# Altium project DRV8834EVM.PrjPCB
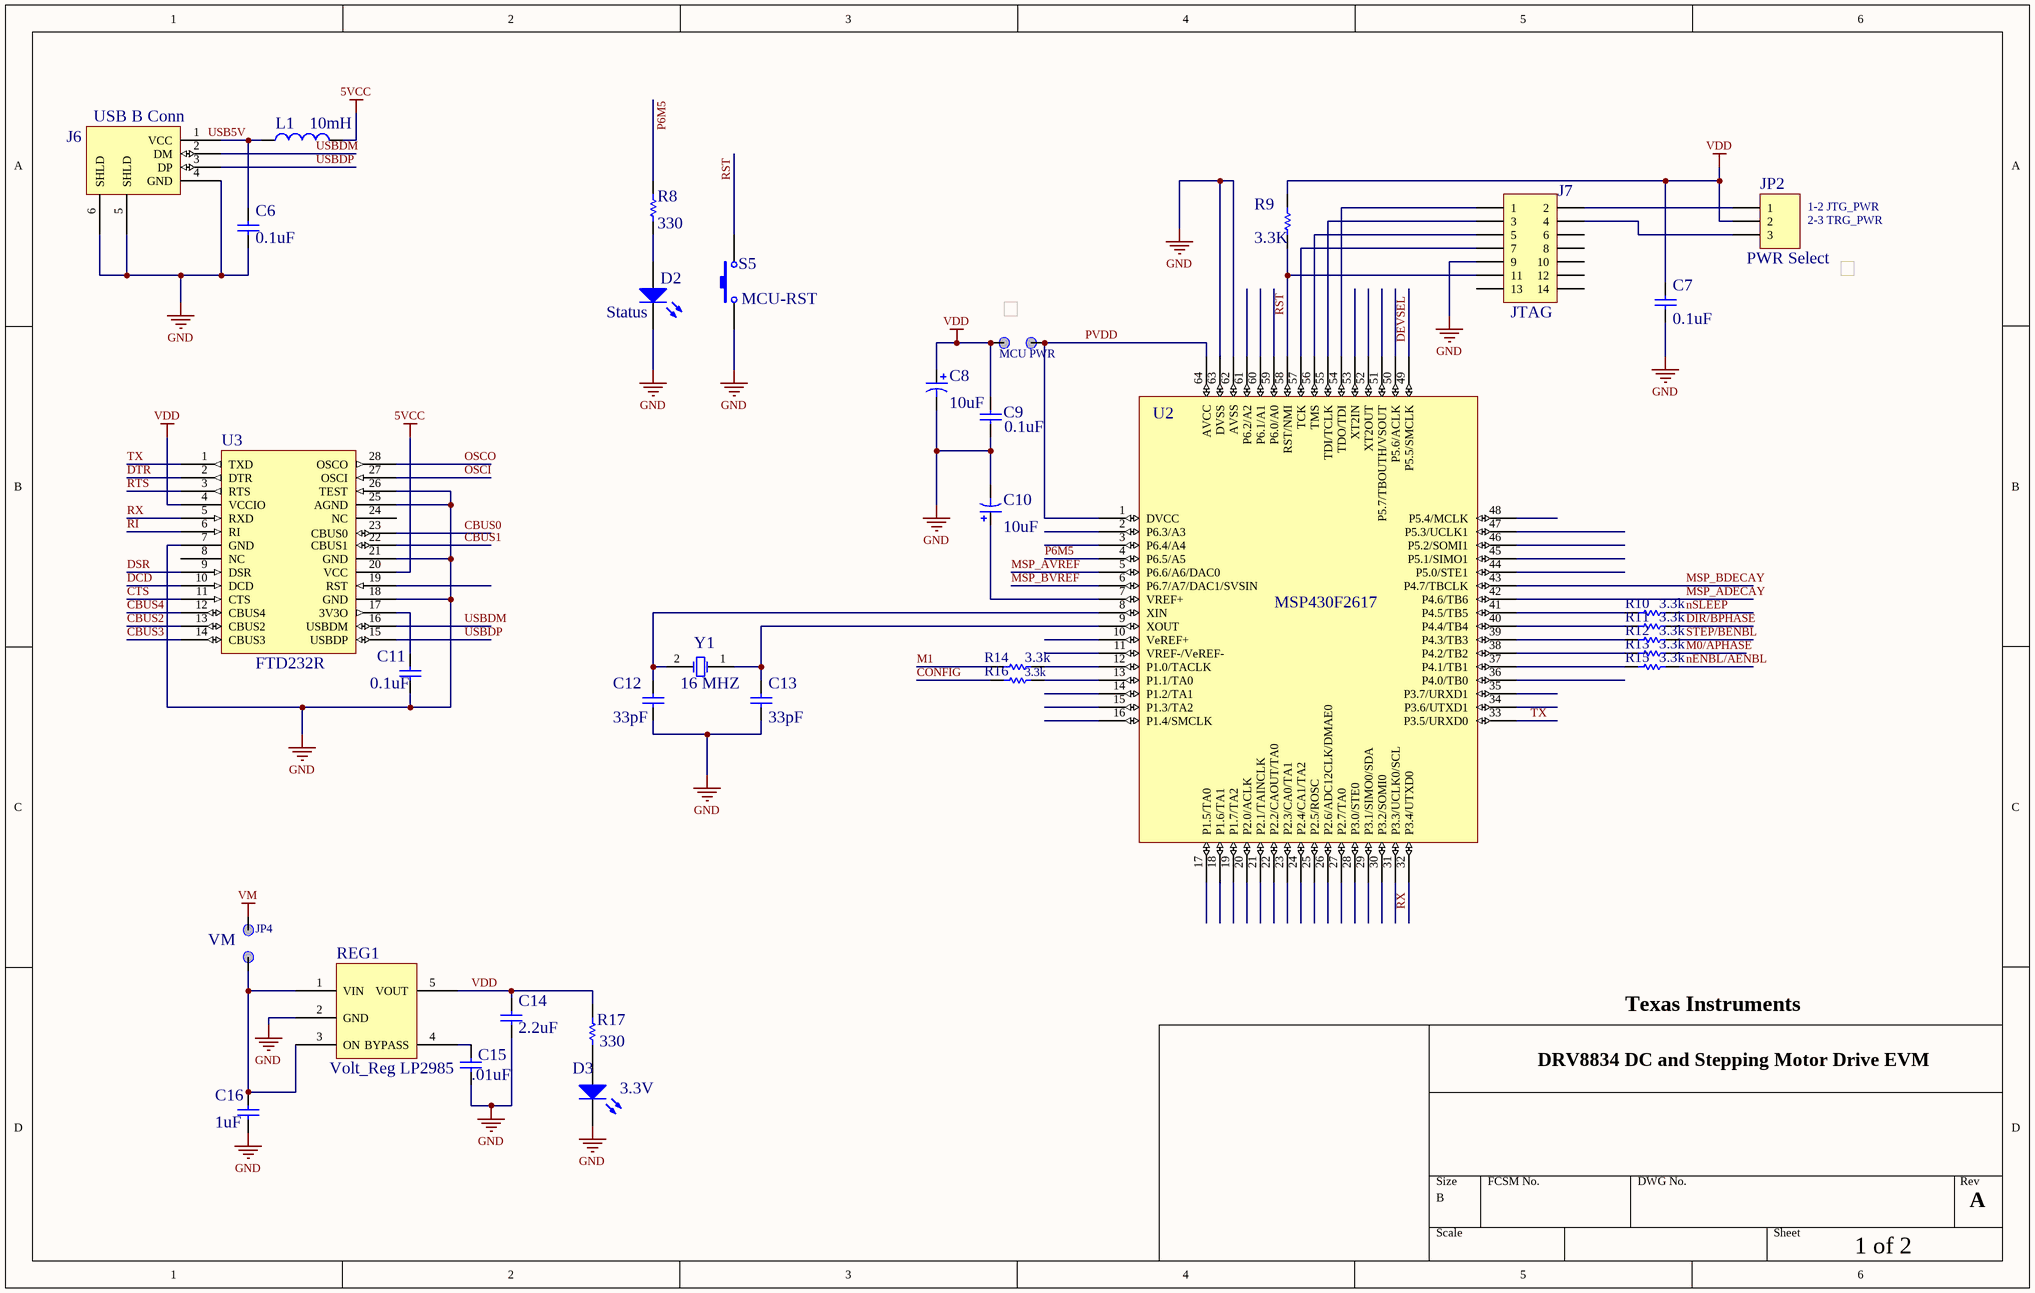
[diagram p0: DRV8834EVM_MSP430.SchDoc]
EVM_Title: DRV8834 Customer EVM- Dual H Bridge Driver
2 sheets, 87 parts. Net scope: global (net labels, ports and power ports of the same name join across sheets).
Board file: DRV8834EVM.PcbDoc
Sheets:
  DRV8834EVM_MSP430.SchDoc
  DRV8834EVM.SchDoc

## Sheet DRV8834EVM_MSP430.SchDoc
size B; PageSetup: Record=PageOptions|CenterHorizontal=True|CenterVertical=True|PrintScale=0.70|XCorrection=1.00|YCorrection=1.00|PrintKind=0|BorderSize=5000000|LeftOffset=0|BottomOffset=0|Orientation=2|PaperLength=1000|PaperWidth=1000|Scale=100|PaperSource=15|PrintQuality=600|MediaType=1|DitherType=10|PaperKind=Letter|PrintScaleMode=1

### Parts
C6  value 0.1uF  [0805]
C7  value 0.1uF  [0805]
C8  value 10uF  [RB .1/.250]  (hidden comment: Cap Pol1)
C9  value 0.1uF  [0805]
C10  value 10uF  [RB .1/.250]  (hidden comment: Cap Pol1)
C11  value 0.1uF  [0805]
C12  value 33pF  [0805]  (hidden comment: Cap)
C13  value 33pF  [0805]  (hidden comment: Cap)
C14  2.2uF  [0603]
C15  .01uF  [0603]
C16  value 1uF  [0603]
D2  Status  [1206_LED]
D3  3.3V  [3.5X2.8X1.9]
J6  USB B Conn  [USB_CONN]
J7  JTAG  [MSP430_JTAG]
JP2  PWR Select  [HDR1X3]
JP3  MCU PWR  [JMP0.2]
JP4  VM  [JMP0.2]
L1  value 10mH  [0805]
R8  value 330  [0805]  (hidden comment: Res2)
R9  value 3.3K  [0805]  (hidden comment: Res2)
R10  value 3.3k  [0603]  (hidden comment: Res1)
R11  value 3.3k  [0603]  (hidden comment: Res1)
R12  value 3.3k  [0603]  (hidden comment: Res1)
R13  value 3.3k  [0603]  (hidden comment: Res1)
R14  value 3.3k  [0603]  (hidden comment: Res1)
R15  value 3.3k  [0603]  (hidden comment: Res1)
R16  value 3.3k  [0603]  (hidden comment: Res1)
R17  value 330  [0805]
REG1  Volt_Reg LP2985  [LP2985]
S5  MCU-RST  [Pana_PB]
SHNT2  3 pin Jumper Shunt  (value not drawn)
SHNT3  3 pin Jumper Shunt  (value not drawn)
U2  MSP430F2617  [MSP430F1612]
U3  FTD232R  [FT232RL]
Y1  16 MHZ  [XTAL]

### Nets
5VCC: L1.2 U3.20(VCC)
GND: C6.1 C7.1 C8.2 C9.1 C10.2 C11.1 C12.1 C13.1 C14.2 C15.2 C16.1 D2.2(K) D3.2(K) J6.4(GND) J6.5(SHLD) J6.6(SHLD) J7.9 REG1.2(GND) S5.1 U2.62(AVSS) U2.63(DVSS) U3.7(GND) U3.18(GND) U3.21(GND) U3.25(AGND) U3.26(TEST)
VDD: C7.2 C8.1 C9.2 C14.1 JP2.2 JP3.2 R9.2 R17.2 REG1.5(VOUT) U3.4(VCCIO)
VM: JP4.2
CBUS0: U3.23(CBUS0)
CBUS1: U3.22(CBUS1)
CBUS2: U3.13(CBUS2)
CBUS3: U3.14(CBUS3)
CBUS4: U3.12(CBUS4)
CONFIG: R16.1
CTS: U3.11(CTS)
DCD: U3.10(DCD)
DEVSEL: U2.49(P5.5/SMCLK)
DIR/BPHASE: R11.2
DSR: U3.9(DSR)
DTR: U3.2(DTR)
M0/APHASE: R13.2
M1: R14.1
MSP_ADECAY: U2.42(P4.6/TB6)
MSP_AVREF: U2.5(P6.6/A6/DAC0)
MSP_BDECAY: U2.43(P4.7/TBCLK)
MSP_BVREF: U2.6(P6.7/A7/DAC1/SVSIN)
nENBL/AENBL: R15.2
nSLEEP: R10.2
OSCI: U3.27(OSCI)
OSCO: U3.28(OSCO)
P6M5: R8.2 U2.4(P6.5/A5)
PVDD: JP3.1 U2.1(DVCC) U2.64(AVCC)
RI: U3.6(RI)
RST: J7.11 R9.1 S5.2 U2.58(RST/NMI)
RTS: U3.3(RTS)
RX: U2.32(P3.4/UTXD0) U3.5(RXD)
STEP/BENBL: R12.2
TX: U2.33(P3.5/URXD0) U3.1(TXD)
USBDM: J6.2(DM) U3.16(USBDM)
USBDP: J6.3(DP) U3.15(USBDP)
NetC6_2: C6.2 J6.1(VCC) L1.1
NetC10_1: C10.1 U2.7(VREF+)
NetC11_2: C11.2 U3.17(3V3O)
NetC12_2: C12.2 U2.8(XIN) Y1.2(OSC2)
NetC13_2: C13.2 U2.9(XOUT) Y1.1(OSC1)
NetC15_1: C15.1 REG1.4(BYPASS)
NetC16_2: C16.2 JP4.1 REG1.1(VIN) REG1.3(ON)
NetD2_1: D2.1(A) R8.1
NetD3_1: D3.1(A) R17.1
NetJ7_1: J7.1 U2.54(TDO/TDI)
NetJ7_2: J7.2 JP2.1
NetJ7_3: J7.3 U2.55(TDI/TCLK)
NetJ7_4: J7.4 JP2.3
NetJ7_5: J7.5 U2.56(TMS)
NetJ7_7: J7.7 U2.57(TCK)
NetR10_1: R10.1 U2.41(P4.5/TB5)
NetR11_1: R11.1 U2.40(P4.4/TB4)
NetR12_1: R12.1 U2.39(P4.3/TB3)
NetR13_1: R13.1 U2.38(P4.2/TB2)
NetR14_2: R14.2 U2.12(P1.0/TACLK)
NetR15_1: R15.1 U2.37(P4.1/TB1)
NetR16_2: R16.2 U2.13(P1.1/TA0)

Not connected (* = marked no-connect by the designer): J7 6 8 10 12 13 14; U2 2(P6.3/A3) 3(P6.4/A4) 10(VeREF+) 11(VREF-/VeREF-) 14(P1.2/TA1) 15(P1.3/TA2) 16(P1.4/SMCLK) 17(P1.5/TA0) 18(P1.6/TA1) 19(P1.7/TA2) 20(P2.0/ACLK) 21(P2.1/TAINCLK) 22(P2.2/CAOUT/TA0) 23(P2.3/CA0/TA1) 24(P2.4/CA1/TA2) 25(P2.5/ROSC) 26(P2.6/ADC12CLK/DMAE0) 27(P2.7/TA0) 28(P3.0/STE0) 29(P3.1/SIMO0/SDA) 30(P3.2/SOMI0) 31(P3.3/UCLK0/SCL) 34(P3.6/UTXD1) 35(P3.7/URXD1) 36(P4.0/TB0) 44(P5.0/STE1) 45(P5.1/SIMO1) 46(P5.2/SOMI1) 47(P5.3/UCLK1) 48(P5.4/MCLK) 50(P5.6/ACLK) 51(P5.7/TBOUTH/VSOUT) 52(XT2OUT) 53(XT2IN) 59(P6.0/A0) 60(P6.1/A1) 61(P6.2/A2); U3 8(NC) 19(RST) 24(NC)

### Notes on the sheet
- 1-2 JTG_PWR
- (near SHNT2) 2-3 TRG_PWR
- Texas Instruments
- DRV8834 DC and Stepping Motor Drive EVM
- A
- 1 of 2
- Labels drawn without touching a wire or pin: USB5V

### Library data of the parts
C6 C7 C9 C11 = Cap: CAP .10UF 50V CERAMIC X7R 0805; MFG Part Number: C0805C104K5RACTU; Manufacturer: Kemet
C8 C10 = Cap Pol1: 10uF, 25V Electrolytic Cap (Radial); MFG Part Number: UVR1E100MDD; Manufacturer: Nichicon
C12 C13 = Cap: CAP CERAMIC 33PF 50V NP0 0805; MFG Part Number: CC0805JRNP09BN330; Manufacturer: Yageo
C14 = Cap: Capacitor; Manufacturer: TDK Corporation; MFG Part Number: C1608X5R0J225K
C15 = Cap: Capacitor; Manufacturer: Murata Electronics North America; MFG Part Number: GRM188R71E103KA01D
C16 = Cap: Capacitor; Manufacturer: TDK Corporation; MFG Part Number: C1608Y5V1C105Z
D2 = LED3: LED RED Clear 1206 SMD; MFG Part Number: HBR1105W-TR; Manufacturer: Stanley Electric & Co; Value: LED RED
D3 = LED3: LED RED Clear 1206 SMD; Manufacturer: Stanley Electric & Co; MFG Part Number: HBR1105W-TR; Value: LED RED
J6 = USB_B_CONN: CONN USB RT ANG RECPT TYPE B BLK; MFG Part Number: 67068-8000; Manufacturer: Molex; Value: USB B
J7 = Header 7X2H: CONN HEADER .100 DUAL STR 14POS; MFG Part Number: PBC07DAAN; Manufacturer: Sullins Connector Solutions; Value: 14 Pos Header
JP2 = Header 3: CONN HEADER .100 SINGL STR 3POS; MFG Part Number: PBC03SAAN; Manufacturer: Sullins Connector Solutions; Value: Connector
JP3 JP4 = JUMPER 2 PIN: Two Pin Jumper; MFG Part Number: PBC02SAAN; Manufacturer: Sullins Connector Solutions; Value: Connector
L1 = Inductor: Ferrite Bead 1.5A 40 ohm 0805 SMD; MFG Part Number: MI0805K400R-10; Manufacturer: Laird-Signal Integrity Products
R8 = Res2: RES 330 OHM 1/8W 5% 0805 SMD; MFG Part Number: RC0805JR-07330RL; Manufacturer: Yageo
R9 = Res2: RES 3.3K OHM 1/8W 5% 0805 SMD; Manufacturer: Yageo; MFG Part Number: RC0805JR-073K3L
R10-R16 = Res1: Resistor; MFG Part Number: ERJ-3GEYJ332V; Manufacturer: Panasonic - ECG
R17 = Res1: RES 330 OHM 1/8W 5% 0805 SMD; Manufacturer: Yageo; MFG Part Number: RC0805JR-07330RL
REG1 = Volt_Reg LP2985: VoltageRegulator; MFG Part Number: LP2985-33DBVR; Manufacturer: Texas Instruments
S5 = SW-PB: SWITCH LIGHT TOUCH 4.3MM 100GF; MFG Part Number: EVQ-11A04M; Manufacturer: Panasonic; Value: Push Button
SHNT2 SHNT3 = ShuntJumper: Shunt Jumper; Manufacturer: Samtec; MFG Part Number: SNT-100-BK-T-H
U2 = MSP430F1612: IC MCU 16BIT 55K FLASH 64-LQFP; MFG Part Number: MSP430F2617TPMR; Manufacturer: Texas Instruments; Value: MSP430 MCU
U3 = FT232R: USB Chip; MFG Part Number: FT232RL R; Manufacturer: FTDI; Value: USB Driver
Y1 = XTAL: CRYSTAL 8.00 MHZ 20PF 49US; MFG Part Number: ECS-160-20-4X; Manufacturer: ECS Inc.

## Sheet DRV8834EVM.SchDoc
size B; PageSetup: Record=PageOptions|CenterHorizontal=True|CenterVertical=True|PrintScale=0.53|XCorrection=1.00|YCorrection=1.00|PrintKind=0|BorderSize=5000000|LeftOffset=0|BottomOffset=0|Orientation=2|PaperLength=1000|PaperWidth=1000|Scale=100|PaperSource=15|PrintQuality=600|MediaType=1|DitherType=10|PaperKind=Letter|PrintScaleMode=1
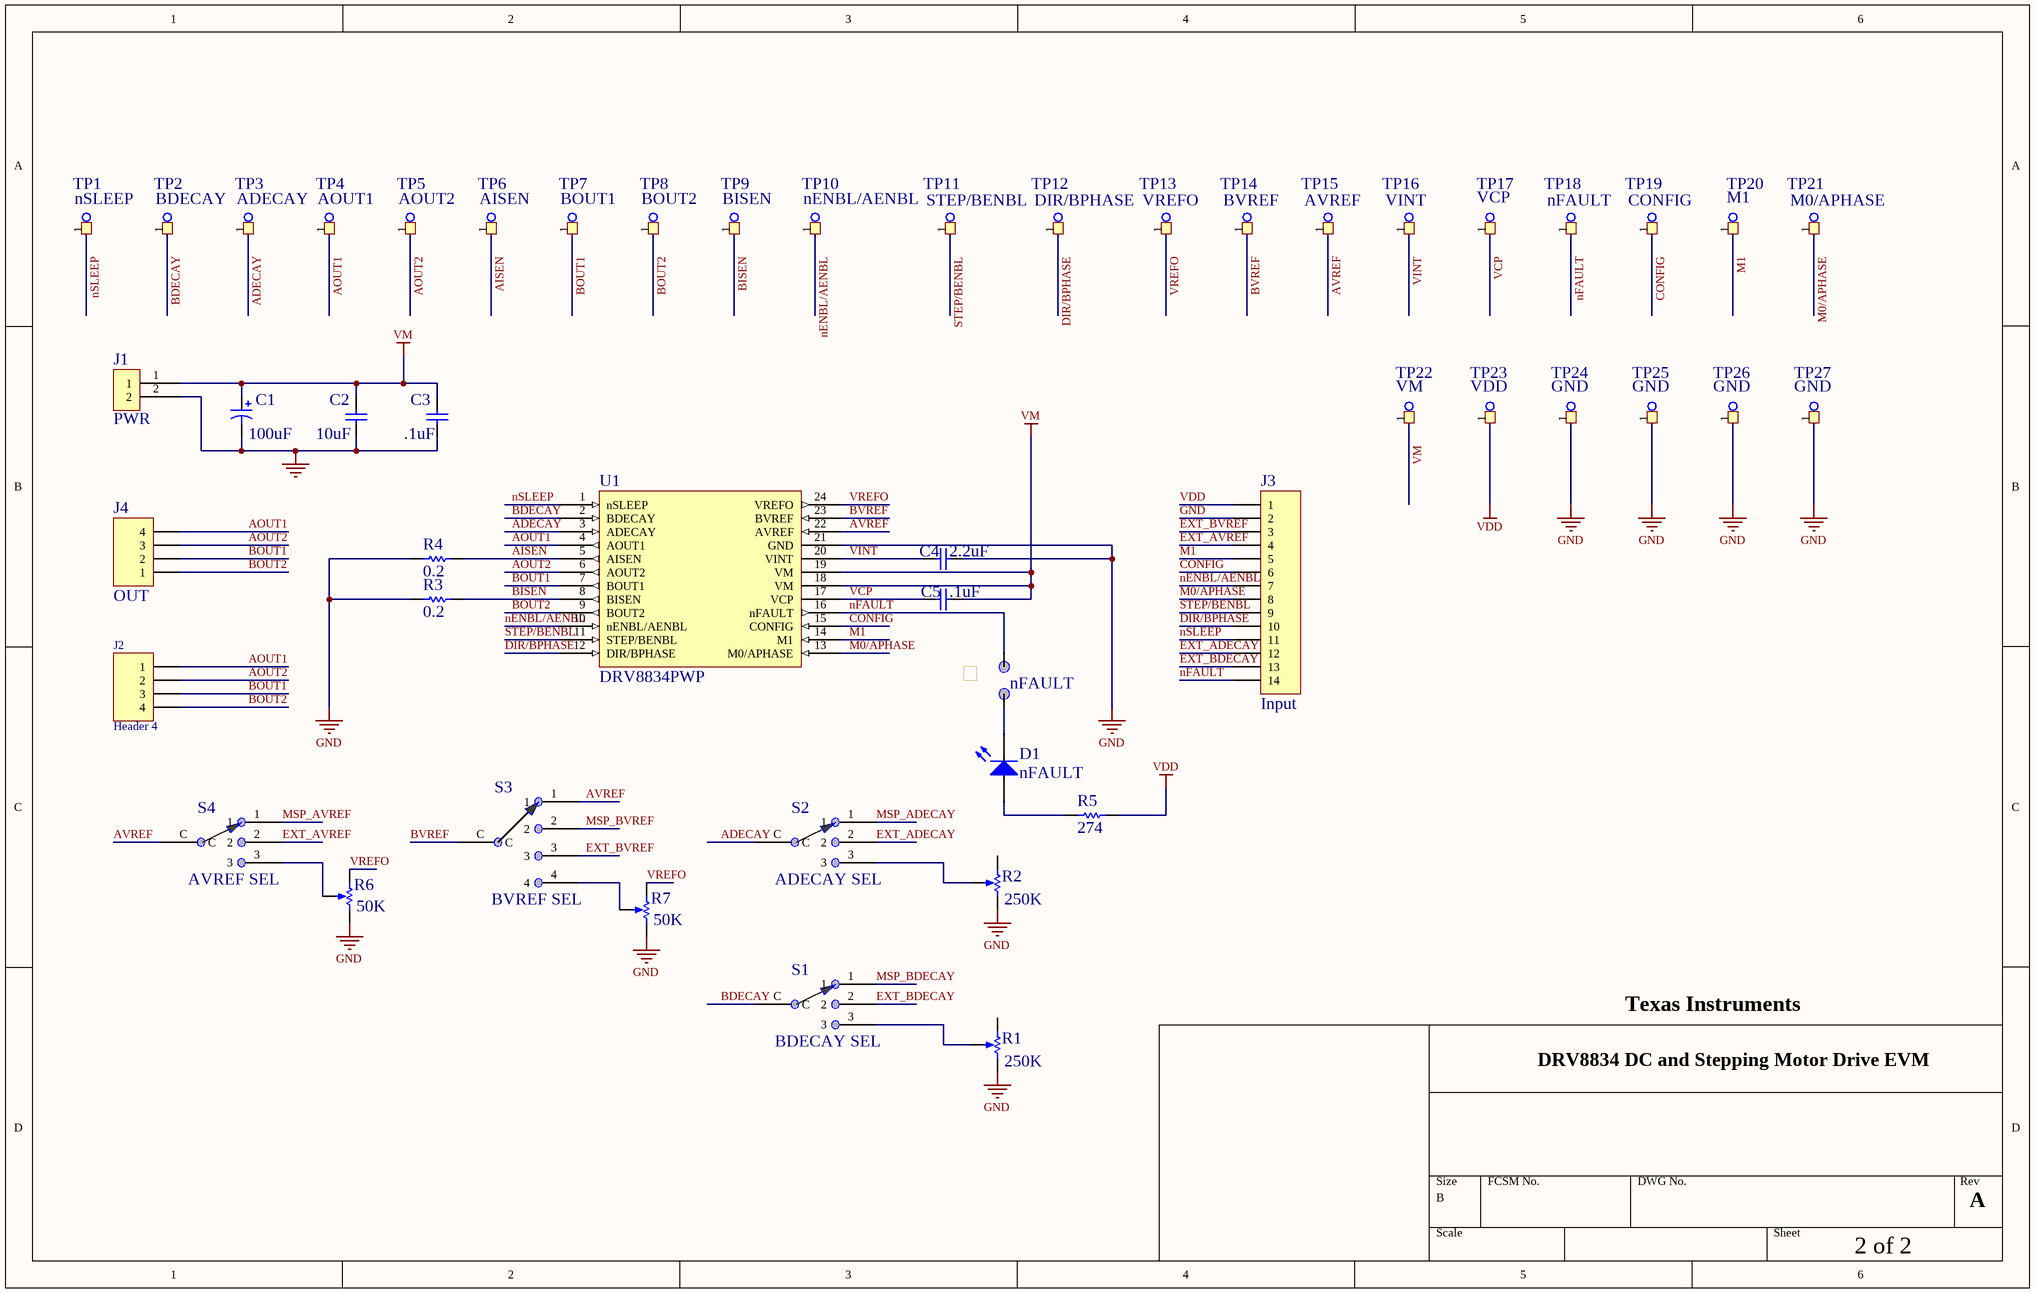
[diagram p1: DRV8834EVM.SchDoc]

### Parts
C1  value 100uF  [RB 2.0mm/5mm_NoPost]
C2  value 10uF  [0805]
C3  value .1uF  [0603]
C4  value 2.2uF  [0603]
C5  value .1uF  [0603]
D1  nFAULT  [1206_LED]
J1  PWR  [PWR_CONN2]
J2  Header 4  [HDR1X4]
J3  Input  [HDR1X14]
J4  OUT  [PWR_CONN4]
JP1  nFAULT  [JMP0.2]
R1  value 250K  [PV36 Pot]
R2  value 250K  [PV36 Pot]
R3  value 0.2  [2512]
R4  value 0.2  [2512]
R5  value 274  [0805]
R6  value 50K  [PV36 Pot]
R7  value 50K  [PV36 Pot]
S1  BDECAY SEL  [SS10 3 Pos Selector - duplicate]
S2  ADECAY SEL  [SS10 3 Pos Selector - duplicate]
S3  BVREF SEL  [SS10 4 POS SELECTOR]
S4  AVREF SEL  [SS10 3 Pos Selector - duplicate]
SHNT1  3 pin Jumper Shunt  (value not drawn)
TP1  nSLEEP  [TEST POINT 0.052]
TP2  BDECAY  [TEST POINT 0.052]
TP3  ADECAY  [TEST POINT 0.052]
TP4  AOUT1  [TEST POINT 0.052]
TP5  AOUT2  [TEST POINT 0.052]
TP6  AISEN  [TEST POINT 0.052]
TP7  BOUT1  [TEST POINT 0.052]
TP8  BOUT2  [TEST POINT 0.052]
TP9  BISEN  [TEST POINT 0.052]
TP10  nENBL/AENBL  [TEST POINT 0.052]
TP11  STEP/BENBL  [TEST POINT 0.052]
TP12  DIR/BPHASE  [TEST POINT 0.052]
TP13  VREFO  [TEST POINT 0.052]
TP14  BVREF  [TEST POINT 0.052]
TP15  AVREF  [TEST POINT 0.052]
TP16  VINT  [TEST POINT 0.052]
TP17  VCP  [TEST POINT 0.052]
TP18  nFAULT  [TEST POINT 0.052]
TP19  CONFIG  [TEST POINT 0.052]
TP20  M1  [TEST POINT 0.052]
TP21  M0/APHASE  [TEST POINT 0.052]
TP22  VM  [TEST POINT 0.052]
TP23  VDD  [TEST POINT 0.052]
TP24  GND  [TEST POINT 0.052]
TP25  GND  [TEST POINT 0.052]
TP26  GND  [TEST POINT 0.052]
TP27  GND  [TEST POINT 0.052]
U1  DRV8834PWP  [DRV8834 (HTSSOP24)]

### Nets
GND: C1.2 C2.1 C3.1 C4.1 J1.2 J3.2 R1.3(BOT) R2.3(BOT) R3.1 R4.1 R6.3(BOT) R7.3(BOT) TP24.1 TP25.1 TP26.1 TP27.1 U1.21(GND)
VDD: J3.1 R5.1 TP23.1
VM: C1.1 C2.2 C3.2 C5.1 J1.1 TP22.1 U1.18(VM) U1.19(VM)
ADECAY: S2.C TP3.1 U1.3(ADECAY)
AISEN: R4.2 TP6.1 U1.5(AISEN)
AOUT1: J2.1 J4.4 TP4.1 U1.4(AOUT1)
AOUT2: J2.2 J4.3 TP5.1 U1.6(AOUT2)
AVREF: S3.1 S4.C TP15.1 U1.22(AVREF)
BDECAY: S1.C TP2.1 U1.2(BDECAY)
BISEN: R3.2 TP9.1 U1.8(BISEN)
BOUT1: J2.3 J4.2 TP7.1 U1.7(BOUT1)
BOUT2: J2.4 J4.1 TP8.1 U1.9(BOUT2)
BVREF: S3.C TP14.1 U1.23(BVREF)
CONFIG: J3.6 TP19.1 U1.15(CONFIG)
DIR/BPHASE: J3.10 TP12.1 U1.12(DIR/BPHASE)
EXT_ADECAY: J3.12 S2.2
EXT_AVREF: J3.4 S4.2
EXT_BDECAY: J3.13 S1.2
EXT_BVREF: J3.3 S3.3
M0/APHASE: J3.8 TP21.1 U1.13(M0/APHASE)
M1: J3.5 TP20.1 U1.14(M1)
MSP_ADECAY: S2.1
MSP_AVREF: S4.1
MSP_BDECAY: S1.1
MSP_BVREF: S3.2
nENBL/AENBL: J3.7 TP10.1 U1.10(nENBL/AENBL)
nFAULT: J3.14 JP1.2 TP18.1 U1.16(nFAULT)
nSLEEP: J3.11 TP1.1 U1.1(nSLEEP)
STEP/BENBL: J3.9 TP11.1 U1.11(STEP/BENBL)
VCP: C5.2 TP17.1 U1.17(VCP)
VINT: C4.2 TP16.1 U1.20(VINT)
VREFO: R6.1(TOP) R7.1(TOP) TP13.1 U1.24(VREFO)
NetD1_1: D1.1(A) R5.2
NetD1_2: D1.2(K) JP1.1
NetR1_2: R1.2(TAP) S1.3
NetR2_2: R2.2(TAP) S2.3
NetR6_2: R6.2(TAP) S4.3
NetR7_2: R7.2(TAP) S3.4

Not connected (* = marked no-connect by the designer): R1 1(TOP); R2 1(TOP)

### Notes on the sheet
- Texas Instruments
- DRV8834 DC and Stepping Motor Drive EVM
- A
- 2 of 2

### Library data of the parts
C1 = Cap Pol1: Polarized Capacitor (Radial); MFG Part Number: RNE1C101MDS1PX; Manufacturer: Nichicon
C2 = Cap: Capacitor; Manufacturer: TDK Corporation; MFG Part Number: C2012X5R1C106M
C3 C5 = Cap: Capacitor; Manufacturer: TDK Corporation; MFG Part Number: C1608X7R1E104K
C4 = Cap1: CAP CER 2.2UF 10V Y5V 0603; Manufacturer: TDK Corporation; MFG Part Number: C1608Y5V1A225Z
D1 = LED3: LED RED CLEAR 1206 SMD; MFG Part Number: HBR1105W-TR; Manufacturer: Stanley Electric & Co; Value: LED RED
J1 = Header 2: TERM BLOCK 5.08MM VERT 2POS PCB; Manufacturer: On Shore Technology Inc; MFG Part Number: OSTTA024163; Value: Connector
J2 = Header 4: Header, 4-Pin; Manufacturer: Sullins Connector Solutions; MFG Part Number: PBC04SAAN; Value: Connector
J3 = Header 14: CONN HEADER .100 SINGL STR 14POS; Manufacturer: Sullins Connector Solutions; MFG Part Number: PBC14SABN; Value: Connector
J4 = Header 4: TERM BLOCK 5.08MM VERT 4POS PCB; Manufacturer: On Shore Technology Inc; MFG Part Number: OSTTA044163; Value: Connector
JP1 = JUMPER 2 PIN: as JP3 on sheet DRV8834EVM_MSP430
R1 R2 = PV37Y103C01B00: TRIMMER 10K OHM 0.25W TH; Manufacturer: Murata Electronics North America; MFG Part Number: PV37Y254C01B00
R3 R4 = Sense Res: RES .2OHM 2W 1% 2512 SMD; Manufacturer: Stackpole; MFG Part Number: CSRN2512FKR200
R5 = Res1: Resistor; Manufacturer: Panasonic - ECG; MFG Part Number: ERJ-6ENF2740V
R6 R7 = PV37Y103C01B00: TRIMMER 10K OHM 0.25W TH; Manufacturer: Murata Electronics North America; MFG Part Number: PV37Y503C01B00
S1 S2 = SS10 3 Pos Selector: SWITCH ROTARY DIP DP3T TOP; Manufacturer: Copal Electronics; MFG Part Number: SS-10-23NP-LE
S3 = SS10 4 Pos Selector: SWITCH ROTARY DIP DP3T TOP; Manufacturer: Copal Electronics; MFG Part Number: S-2150
S4 = SS10 3 Pos Selector: SWITCH ROTARY DIP SP4T TOP KNOB; Manufacturer: Copal Electronics; MFG Part Number: SS-10-23NP-LE
SHNT1 = ShuntJumper: as SHNT2 on sheet DRV8834EVM_MSP430
TP1-TP22 = TEST POINT: Glass Beaded Test Point; Manufacturer: Keystone; MFG Part Number: 5007; Value: WHITE
TP23 = TEST POINT: Glass Beaded Test Point; Manufacturer: Keystone; MFG Part Number: 5005; Value: RED
TP24-TP27 = TEST POINT: Glass Beaded Test Point; Manufacturer: Keystone; MFG Part Number: 5006; Value: BLACK
U1 = DRV8834PWP: Stepping and DC motor Driver; Manufacturer: Texas Instruments

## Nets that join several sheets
GND: DRV8834EVM_MSP430 (26 pins), DRV8834EVM (17 pins)
VDD: DRV8834EVM_MSP430 (10 pins), DRV8834EVM (J3.1 R5.1 TP23.1)
VM: DRV8834EVM_MSP430 (JP4.2), DRV8834EVM (8 pins)
CONFIG: DRV8834EVM_MSP430 (R16.1), DRV8834EVM (J3.6 TP19.1 U1.15)
DIR/BPHASE: DRV8834EVM_MSP430 (R11.2), DRV8834EVM (J3.10 TP12.1 U1.12)
M0/APHASE: DRV8834EVM_MSP430 (R13.2), DRV8834EVM (J3.8 TP21.1 U1.13)
M1: DRV8834EVM_MSP430 (R14.1), DRV8834EVM (J3.5 TP20.1 U1.14)
MSP_ADECAY: DRV8834EVM_MSP430 (U2.42), DRV8834EVM (S2.1)
MSP_AVREF: DRV8834EVM_MSP430 (U2.5), DRV8834EVM (S4.1)
MSP_BDECAY: DRV8834EVM_MSP430 (U2.43), DRV8834EVM (S1.1)
MSP_BVREF: DRV8834EVM_MSP430 (U2.6), DRV8834EVM (S3.2)
nENBL/AENBL: DRV8834EVM_MSP430 (R15.2), DRV8834EVM (J3.7 TP10.1 U1.10)
nSLEEP: DRV8834EVM_MSP430 (R10.2), DRV8834EVM (J3.11 TP1.1 U1.1)
STEP/BENBL: DRV8834EVM_MSP430 (R12.2), DRV8834EVM (J3.9 TP11.1 U1.11)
